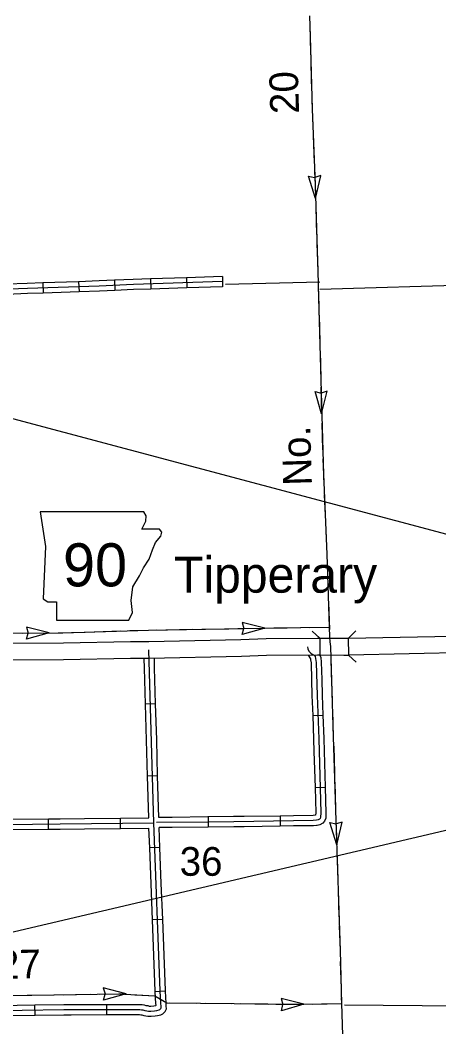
# Model space of a CAD drawing. Extents: x -5566 to 1759129, y -3726 to 731467.
# Drawn here: x -4927.6 to -4880.9, y 268.1 to 380.4 of the extents above; entities that cross this region are included whole.
import ezdxf

# ---------------------------------------------------------------- set-up
doc = ezdxf.new("R2010")
doc.units = 0
doc.layers.add('Default', color=7, linetype='Continuous')

msp = doc.modelspace()

# ---------------------------------------------------------------- linework, layer by layer
at = {"layer": 'Default'}
for p, q in [((-5045.08, 367.09), (-4814.18, 305.51)), ((-4894.68, 360.53), (-4895.44, 363.03)), ((-4895.44, 363.02), (-4894.77, 362.87)), ((-4894.09, 363.08), (-4894.76, 362.87)), ((-4894.68, 360.53), (-4894.09, 363.07)), ((-4909.07, 351.69), (-4909.03, 350.56)), ((-4905.06, 351.83), (-4905.03, 350.69)), ((-4925.1, 351.11), (-4925.06, 349.98)), ((-4921.09, 351.25), (-4921.05, 350.11)), ((-4917.09, 351.4), (-4917.04, 350.26)), ((-4913.08, 351.56), (-4913.04, 350.42)), ((-4893.99, 336.49), (-4894.73, 338.98)), ((-4894.73, 338.98), (-4894.05, 338.82)), ((-4893.38, 339.02), (-4894.04, 338.82)), ((-4893.99, 336.49), (-4893.38, 339.02)), ((-4924.38, 312.05), (-4926.9, 312.71)), ((-4926.9, 312.71), (-4926.72, 312.04)), ((-4900.33, 312.6), (-4902.86, 313.23)), ((-4902.86, 313.23), (-4902.67, 312.57)), ((-4900.33, 312.6), (-4902.84, 311.88)), ((-4902.84, 311.88), (-4902.67, 312.56)), ((-4924.38, 312.05), (-4926.9, 311.36)), ((-4926.9, 311.36), (-4926.72, 312.04)), ((-5037.98, 253.01), (-4814.18, 305.51)), ((-4912.51, 304.14), (-4913.64, 304.11)), ((-4894.99, 302.83), (-4893.85, 302.87)), ((-4912.28, 296.12), (-4913.42, 296.09)), ((-4894.73, 294.82), (-4893.59, 294.85)), ((-4924.44, 290.17), (-4924.45, 291.31)), ((-4916.42, 290.25), (-4916.43, 291.39)), ((-4906.65, 291.52), (-4906.63, 290.38)), ((-4898.63, 291.63), (-4898.61, 290.49)), ((-4891.72, 290.94), (-4892.38, 290.74)), ((-4892.31, 288.4), (-4891.72, 290.94)), ((-4892.31, 288.4), (-4893.07, 290.9)), ((-4893.07, 290.9), (-4892.39, 290.74)), ((-4912.03, 288.11), (-4913.16, 288.07)), ((-4911.72, 280.1), (-4912.86, 280.05)), ((-4915.81, 271.8), (-4918.34, 272.44)), ((-4918.34, 272.44), (-4918.15, 271.77)), ((-4911.42, 272.1), (-4912.56, 272.03)), ((-4915.81, 271.8), (-4918.32, 271.09)), ((-4918.32, 271.09), (-4918.15, 271.76)), ((-4895.97, 270.63), (-4898.5, 271.26)), ((-4898.5, 271.26), (-4898.31, 270.59)), ((-4925.94, 269.42), (-4925.96, 270.56)), ((-4917.93, 269.47), (-4917.93, 270.61)), ((-4895.97, 270.63), (-4898.48, 269.91)), ((-4898.48, 269.91), (-4898.31, 270.58))]:
    msp.add_line(p, q, dxfattribs=at)
for points in [[(-4895.36, 380.91), (-4895.29, 378.59), (-4895.05, 370.49), (-4894.73, 362.1), (-4894.38, 351.08), (-4894.37, 350.8), (-4893.8, 329.73), (-4893.41, 320.85), (-4893.11, 311.6), (-4893.08, 311.05), (-4892.99, 310.54), (-4892.91, 306.73), (-4892.69, 300.47), (-4892.4, 291.12), (-4891.94, 276.64), (-4891.79, 270.71), (-4891.16, 250.51)], [(-4895.32, 379.57), (-4895.29, 378.59), (-4895.23, 376.56)], [(-4895.2, 375.56), (-4895.11, 372.56)], [(-4895.08, 371.55), (-4895.05, 370.49), (-4894.97, 368.55)], [(-4894.94, 367.55), (-4894.82, 364.54)], [(-4894.79, 363.54), (-4894.73, 362.1), (-4894.68, 360.53)], [(-4894.65, 359.53), (-4894.6, 358.03)], [(-4894.6, 358.03), (-4894.55, 356.53)], [(-4894.52, 355.52), (-4894.43, 352.52)], [(-4909.07, 351.69), (-4913.08, 351.56)], [(-4905.06, 351.83), (-4909.07, 351.69)], [(-4905.04, 351.26), (-4914.98, 350.93), (-4918.79, 350.76), (-4926.81, 350.49), (-4934.9, 350.19), (-4936.37, 350.22), (-4937.6, 350.26), (-4938.2, 350.3), (-4938.43, 350.31)], [(-4925.1, 351.11), (-4926.83, 351.06), (-4929.11, 350.97)], [(-4921.09, 351.25), (-4925.1, 351.11)], [(-4917.09, 351.4), (-4918.82, 351.33), (-4921.09, 351.25)], [(-4913.08, 351.56), (-4915.01, 351.5), (-4917.09, 351.4)], [(-4909.03, 350.56), (-4913.04, 350.42)], [(-4905.03, 350.69), (-4909.03, 350.56)], [(-4904.73, 350.99), (-4894.21, 351.23)], [(-4894.39, 351.52), (-4894.38, 351.08), (-4894.37, 350.8), (-4894.31, 348.51)], [(-4894.18, 350.41), (-4876.61, 350.92)], [(-4925.06, 349.98), (-4926.79, 349.92), (-4929.07, 349.83)], [(-4921.05, 350.11), (-4925.06, 349.98)], [(-4917.04, 350.26), (-4918.77, 350.19), (-4921.05, 350.11)], [(-4913.04, 350.42), (-4914.96, 350.36), (-4917.04, 350.26)], [(-4894.28, 347.51), (-4894.2, 344.5)], [(-4894.17, 343.5), (-4894.09, 340.49)], [(-4894.07, 339.49), (-4893.99, 336.49)], [(-4893.96, 335.48), (-4893.92, 333.98)], [(-4893.92, 333.98), (-4893.88, 332.48)], [(-4893.85, 331.48), (-4893.8, 329.73), (-4893.75, 328.47)], [(-4893.7, 327.47), (-4893.57, 324.46)], [(-4893.53, 323.46), (-4893.41, 320.85), (-4893.4, 320.46)], [(-4893.23, 315.45), (-4893.13, 312.44)], [(-4933.88, 312), (-4928.77, 312.03), (-4922.87, 312.06), (-4913.29, 312.38), (-4896.34, 312.67), (-4893.16, 312.7)], [(-4919.37, 312.18), (-4916.37, 312.28)], [(-4915.37, 312.31), (-4913.29, 312.38), (-4912.36, 312.4)], [(-4911.36, 312.41), (-4908.35, 312.47)], [(-4907.35, 312.48), (-4904.34, 312.53)], [(-4903.34, 312.55), (-4900.33, 312.6)], [(-4899.33, 312.62), (-4897.83, 312.64)], [(-4897.83, 312.64), (-4896.34, 312.67), (-4896.32, 312.67)], [(-4895.32, 312.68), (-4893.16, 312.7)], [(-4890.99, 311.49), (-4890.19, 312.3)], [(-4933.59, 310.92), (-4929.26, 310.92), (-4922.79, 310.96), (-4915.32, 311.09), (-4913.26, 311.11), (-4902.99, 311.33), (-4900.18, 311.45), (-4894.48, 311.47), (-4894.21, 311.47)], [(-4894.21, 311.47), (-4894.18, 309.57), (-4894.45, 309.57), (-4900.14, 309.55), (-4902.93, 309.43), (-4913.23, 309.21), (-4915.3, 309.19), (-4922.77, 309.06), (-4929.26, 309.02), (-4933.59, 309.02)], [(-4927.39, 312.04), (-4924.38, 312.05)], [(-4923.38, 312.05), (-4922.87, 312.06), (-4921.88, 312.09)], [(-4921.88, 312.09), (-4920.38, 312.14)], [(-4895.03, 312.26), (-4894.21, 311.47)], [(-4894.21, 311.47), (-4893, 311.49), (-4891, 311.49)], [(-4890.96, 309.59), (-4891, 311.49), (-4877.55, 311.75), (-4877.72, 311.53), (-4877.86, 311.25), (-4877.92, 310.95), (-4877.92, 310.68), (-4877.87, 310.42), (-4877.72, 310.1), (-4877.51, 309.86)], [(-4932.09, 269.9), (-4922.73, 270.03), (-4914.42, 270.04), (-4914.28, 270.03), (-4914.08, 270.02), (-4913.94, 270), (-4913.71, 269.94), (-4913.49, 269.91), (-4913.31, 269.87), (-4913.04, 269.85), (-4912.64, 269.9), (-4912.39, 269.94), (-4912.13, 270), (-4912.02, 270.05), (-4911.92, 270.14), (-4911.88, 270.23), (-4911.89, 270.37), (-4911.91, 270.73), (-4911.99, 272.12), (-4912.7, 290.85), (-4913.25, 310.16)], [(-4895.56, 310.52), (-4895.52, 310.27), (-4895.41, 310.04), (-4895.18, 309.81), (-4894.97, 309.66), (-4894.83, 309.56), (-4894.72, 309.41), (-4894.66, 309.19), (-4894.6, 308.76), (-4894.5, 305.08), (-4894.32, 300.24), (-4894.08, 291.97), (-4894.11, 291.51), (-4894.16, 291.35), (-4894.23, 291.28), (-4894.38, 291.19), (-4894.57, 291.15), (-4894.92, 291.12), (-4897.12, 291.09), (-4903.8, 290.99), (-4906.67, 290.95), (-4912.41, 290.89)], [(-4913.76, 308.11), (-4913.79, 309.2)], [(-4912.62, 308.15), (-4912.65, 309.22)], [(-4895.48, 309.56), (-4895.24, 309.15), (-4895.24, 309.15), (-4895.22, 309.07), (-4895.17, 308.71), (-4895.12, 306.84)], [(-4894.18, 309.57), (-4892.99, 309.6), (-4891.52, 309.58), (-4890.96, 309.59)], [(-4894.18, 309.57), (-4894.1, 309.31), (-4894.03, 308.8), (-4893.98, 306.87)], [(-4894.18, 309.57), (-4894.18, 309.57)], [(-4892.97, 309.6), (-4892.95, 308.44)], [(-4890.16, 308.79), (-4890.98, 309.59)], [(-4877.51, 309.86), (-4890.96, 309.59)], [(-4913.64, 304.11), (-4913.76, 308.11)], [(-4912.51, 304.14), (-4912.62, 308.15)], [(-4895.12, 306.84), (-4895.07, 305.07), (-4894.99, 302.83)], [(-4893.98, 306.87), (-4893.93, 305.1), (-4893.85, 302.87)], [(-4892.92, 307.44), (-4892.91, 306.73), (-4892.83, 304.43)], [(-4913.53, 300.1), (-4913.64, 304.11)], [(-4912.39, 300.13), (-4912.51, 304.14)], [(-4892.79, 303.43), (-4892.69, 300.47), (-4892.68, 300.43)], [(-4894.99, 302.83), (-4894.89, 300.22), (-4894.85, 298.83)], [(-4893.85, 302.87), (-4893.75, 300.26), (-4893.71, 298.86)], [(-4913.42, 296.09), (-4913.53, 300.1)], [(-4912.28, 296.12), (-4912.39, 300.13)], [(-4894.85, 298.83), (-4894.73, 294.82)], [(-4893.71, 298.86), (-4893.59, 294.85)], [(-4892.65, 299.42), (-4892.56, 296.42)], [(-4913.28, 291.42), (-4913.42, 296.09)], [(-4912.15, 291.47), (-4912.28, 296.12)], [(-4894.73, 294.82), (-4894.65, 291.98), (-4894.67, 291.71), (-4894.66, 291.71)], [(-4893.59, 294.85), (-4893.51, 291.96), (-4893.54, 291.4), (-4893.66, 291.05), (-4893.86, 290.83), (-4894.18, 290.65), (-4894.5, 290.58), (-4894.57, 290.58)], [(-4892.53, 295.42), (-4892.44, 292.41)], [(-4928.46, 291.26), (-4924.45, 291.31)], [(-4924.45, 291.31), (-4923.17, 291.32), (-4920.44, 291.35)], [(-4920.44, 291.35), (-4916.43, 291.39)], [(-4916.43, 291.39), (-4913.28, 291.42)], [(-4910.66, 291.48), (-4912.15, 291.47)], [(-4906.65, 291.52), (-4906.67, 291.52), (-4910.66, 291.48)], [(-4902.64, 291.58), (-4903.81, 291.56), (-4906.65, 291.52)], [(-4898.63, 291.63), (-4902.64, 291.58)], [(-4894.66, 291.71), (-4894.95, 291.69), (-4897.13, 291.66), (-4898.63, 291.63)], [(-4892.41, 291.41), (-4892.4, 291.12), (-4892.31, 288.4)], [(-4932.47, 290.65), (-4923.16, 290.75), (-4912.7, 290.85)], [(-4928.45, 290.12), (-4924.44, 290.17)], [(-4924.44, 290.17), (-4923.16, 290.18), (-4920.43, 290.21)], [(-4920.43, 290.21), (-4916.42, 290.25)], [(-4916.42, 290.25), (-4913.25, 290.28)], [(-4913.16, 288.07), (-4913.25, 290.28)], [(-4910.65, 290.34), (-4912.11, 290.33)], [(-4912.03, 288.11), (-4912.11, 290.33)], [(-4906.63, 290.38), (-4906.66, 290.38), (-4910.65, 290.34)], [(-4902.62, 290.44), (-4903.8, 290.42), (-4906.63, 290.38)], [(-4898.61, 290.49), (-4902.62, 290.44)], [(-4894.57, 290.58), (-4894.89, 290.55), (-4897.12, 290.52), (-4898.61, 290.49)], [(-4913.01, 284.06), (-4913.16, 288.07)], [(-4911.87, 284.1), (-4912.03, 288.11)], [(-4892.28, 287.4), (-4892.23, 285.9)], [(-4892.23, 285.9), (-4892.18, 284.4)], [(-4912.86, 280.05), (-4913.01, 284.06)], [(-4911.72, 280.1), (-4911.87, 284.1)], [(-4892.15, 283.39), (-4892.06, 280.39)], [(-4912.71, 276.05), (-4912.86, 280.05)], [(-4911.57, 276.09), (-4911.72, 280.1)], [(-4892.02, 279.39), (-4891.94, 276.64), (-4891.93, 276.38)], [(-4912.56, 272.03), (-4912.56, 272.09), (-4912.71, 276.05)], [(-4911.42, 272.1), (-4911.42, 272.15), (-4911.57, 276.09)], [(-4891.91, 275.38), (-4891.83, 272.37)], [(-4914.05, 269.44), (-4913.82, 269.38), (-4913.6, 269.35), (-4913.39, 269.3), (-4913.02, 269.28), (-4912.56, 269.34), (-4912.28, 269.38), (-4911.94, 269.46), (-4911.71, 269.57), (-4911.44, 269.8), (-4911.31, 270.13), (-4911.32, 270.4), (-4911.34, 270.76), (-4911.42, 272.1)], [(-4913.79, 270.55), (-4913.59, 270.5), (-4913.39, 270.47), (-4913.24, 270.43), (-4913.05, 270.42), (-4912.72, 270.46), (-4912.5, 270.5), (-4912.46, 270.51), (-4912.47, 270.7), (-4912.56, 272.03)], [(-4931.17, 271.56), (-4916.6, 271.79), (-4912.59, 271.56), (-4911.25, 270.79)], [(-4926.84, 271.63), (-4923.83, 271.67)], [(-4922.83, 271.69), (-4919.82, 271.74)], [(-4918.82, 271.75), (-4916.6, 271.79), (-4915.81, 271.8)], [(-4914.81, 271.69), (-4913.31, 271.6)], [(-4913.31, 271.6), (-4912.53, 271.55)], [(-4911.25, 270.79), (-4896.23, 270.63), (-4891.79, 270.71)], [(-4911.01, 270.79), (-4908, 270.76)], [(-4907, 270.75), (-4903.99, 270.71)], [(-4891.81, 271.37), (-4891.79, 270.71), (-4891.72, 268.36)], [(-4929.97, 270.5), (-4925.96, 270.56)], [(-4925.96, 270.56), (-4922.74, 270.6), (-4921.94, 270.6)], [(-4921.94, 270.6), (-4917.93, 270.61)], [(-4917.93, 270.61), (-4914.41, 270.61), (-4914.25, 270.6), (-4914.02, 270.59), (-4913.83, 270.56), (-4913.79, 270.55)], [(-4902.99, 270.7), (-4899.89, 270.62)], [(-4899.1, 270.62), (-4898.31, 270.59), (-4896.23, 270.63), (-4895.97, 270.63)], [(-4894.97, 270.65), (-4891.79, 270.71)], [(-4891.43, 270.56), (-4878.46, 270.45)], [(-4929.95, 269.36), (-4925.94, 269.42)], [(-4925.94, 269.42), (-4922.73, 269.46), (-4921.94, 269.46)], [(-4921.94, 269.46), (-4917.93, 269.47)], [(-4917.93, 269.47), (-4914.43, 269.47), (-4914.31, 269.47), (-4914.15, 269.46), (-4914.06, 269.44), (-4914.05, 269.44)]]:
    msp.add_lwpolyline(points, dxfattribs=at)
msp.add_lwpolyline([(-4925.37, 325.56), (-4924.79, 321.71), (-4925.05, 315.86), (-4924.53, 315.54), (-4923.57, 315.54), (-4923.57, 313.48), (-4915.48, 313.48), (-4915.09, 314.32), (-4915.22, 315.67), (-4915.03, 317.21), (-4914.32, 318.43), (-4913.87, 319.33), (-4913.23, 320.29), (-4912.84, 321.32), (-4912.52, 322.16), (-4911.94, 322.86), (-4911.81, 323.31), (-4912.07, 323.63), (-4914.06, 323.63), (-4913.61, 324.53), (-4913.55, 325.11), (-4913.81, 325.56)], close=True, dxfattribs=at)

# ---------------------------------------------------------------- texts
for s, height, rotation, p in [('20', 3.205, 91.7789, (-4896.5, 370.02)), ('No.', 3.205, 91.7789, (-4895.07, 328.53)), ('Ditch    No.       27', 3.2048, 1.2682, (-4959.57, 272.78))]:
    msp.add_text(s, height=height, rotation=rotation, dxfattribs=at).set_placement(p)
for s, height, p in [('90', 4.807, (-4922.84, 317.25)), ('Tipperary', 4.01, (-4910.45, 316.55)), ('36', 3.205, (-4909.82, 284.96))]:
    msp.add_text(s, height=height, dxfattribs=at).set_placement(p)

doc.saveas('drawing.dxf')
